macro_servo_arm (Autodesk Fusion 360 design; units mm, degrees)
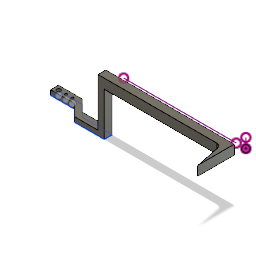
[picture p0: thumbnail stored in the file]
sketch "Sketch1" plane through (0, 0, 0) normal (0, 1, 0) x axis (1, 0, 0)
  line L1 (-10, 0) -> (-24.9061, 0)
  line L2 (-24.9061, -5) -> (-24.9061, 0)
  line L3 (-10, -5) -> (-24.9061, -5)
  line L4 (-2.9289, -7.0711) -> (-10, 0)
  line L5 (-2.9289, -12.0711) -> (-10, -5)
  line L6 (15.6446, -12.0711) -> (15.6446, -7.0711)
  line L7 (15.6446, -7.0711) -> (-2.9289, -7.0711)
  line L8 (-2.9289, -12.0711) -> (15.6446, -12.0711)
  circle C1 centre (-17.5324, -2.7002) radius 0.75
  circle C2 centre (-13.5324, -2.7002) radius 0.75
  circle C3 centre (-22.0324, -2.7002) radius 1.2
  point P6 (-17.5324, -2.7002)
  point P10 (-22.0324, -2.7002)
  dimension "d31" diameter C3 = 2.4
  dimension "d32" distance P6 P10 = 4.5
  dimension "d34" diameter C2 = 1.5
  dimension "d35" diameter C1 = 1.5
extrude "Extrude2" new body sketch "Sketch1" along normal blind 3
extrude "Extrude1" new body sketch "Sketch1" profile of L1 L2 L3 C1 C2 L4 L5 L7 L8 C3 along normal blind 3
sketch "Sketch2" plane through (0, 3, 0) normal (0, 1, 0) x axis (-1, 0, 0)
  line L1 (24.9061, 5) -> (24.9061, 0)
  line L2 (10, 5) -> (24.9061, 5)
  line L3 (2.9289, 12.0711) -> (10, 5)
  line L4 (-15.6446, 12.0711) -> (2.9289, 12.0711)
  line L5 (-15.6446, 7.0711) -> (-15.6446, 12.0711)
  line L6 (2.9289, 7.0711) -> (-15.6446, 7.0711)
  line L7 (10, 0) -> (2.9289, 7.0711)
  line L8 (24.9061, 0) -> (10, 0)
  line L9 (-11.6446, 12.0711) -> (-15.6446, 12.0711)
  line L10 (-11.6446, 7.0711) -> (-11.6446, 12.0711)
  line L11 (-15.6446, 7.0711) -> (-11.6446, 7.0711)
  line L12 (-15.6446, 12.0711) -> (-15.6446, 7.0711)
  circle C1 centre (13.5324, 2.7002) radius 0.75
  circle C2 centre (17.5324, 2.7002) radius 0.75
  circle C3 centre (22.0324, 2.7002) radius 1.2
  point P13 (-15.6446, 12.0711)
  point P14 (-11.6446, 12.0711)
  point P16 (-15.6446, 7.0711)
  dimension "d40" distance P13 P14 = 4
  dimension "d41" distance P13 P16 = 5
extrude "Extrude3" add sketch "Sketch2" profile of L4 L5 L6 L9 L10 L11 L12 along normal blind 30
sketch "Sketch3" plane through (15.6446, 0, 0) normal (1, 0, 0) x axis (0, 0, -1)
  line L1 (-7.0711, 33) -> (-7.0711, 0)
  line L2 (-12.0711, 33) -> (-7.0711, 33)
  line L3 (-12.0711, 0) -> (-12.0711, 33)
  line L4 (-7.0711, 0) -> (-12.0711, 0)
  line L5 (-7.0711, 33) -> (-12.0711, 33)
  line L6 (-7.0711, 27) -> (-7.0711, 33)
  line L7 (-12.0711, 27) -> (-7.0711, 27)
  line L8 (-12.0711, 33) -> (-12.0711, 27)
  point P6 (-12.0711, 33)
  point P7 (-7.0711, 33)
  point P9 (-12.0711, 27)
  dimension "d44" distance P6 P7 = 5
  dimension "d45" distance P6 P9 = 6
extrude "Extrude4" add sketch "Sketch3" profile of L1 L2 L3 L5 L6 L7 L8 along normal blind 76
sketch "Sketch4" plane through (0, 0, 12.0711) normal (0, 0, 1) x axis (1, 0, 0)
  line L1 (15.6446, 27) -> (15.6446, 0)
  line L2 (91.6446, 27) -> (15.6446, 27)
  line L3 (91.6446, 33) -> (91.6446, 27)
  line L4 (11.6446, 33) -> (91.6446, 33)
  line L5 (11.6446, 3) -> (11.6446, 33)
  line L6 (-2.9289, 3) -> (11.6446, 3)
  line L7 (-2.9289, 0) -> (-2.9289, 3)
  line L8 (15.6446, 0) -> (-2.9289, 0)
  line L9 (88.6446, 33) -> (91.6446, 33)
  line L10 (88.6446, 27) -> (88.6446, 33)
  line L11 (91.6446, 27) -> (88.6446, 27)
  line L12 (91.6446, 33) -> (91.6446, 27)
extrude "Extrude5" add sketch "Sketch4" profile of L2 L3 L4 L9 L10 L11 L12 distance 3
sketch "Sketch5" plane through (0, 33, 0) normal (0, 1, 0) x axis (-1, 0, 0)
  line L1 (-91.6446, 7.0711) -> (-91.6446, 15.0711)
  line L2 (-11.6446, 7.0711) -> (-91.6446, 7.0711)
  line L3 (-11.6446, 12.0711) -> (-11.6446, 7.0711)
  line L4 (-88.6446, 12.0711) -> (-11.6446, 12.0711)
  line L5 (-88.6446, 15.0711) -> (-88.6446, 12.0711)
  line L6 (-91.6446, 15.0711) -> (-88.6446, 15.0711)
  line L7 (-91.6446, 30.0711) -> (-91.6446, 15.0711)
  line L8 (-91.6446, 30.0711) -> (-88.6446, 15.0711)
  point P8 (-91.6446, 15.0711)
  point P9 (-91.6446, 30.0711)
  dimension "d50" distance P8 P9 = 15
extrude "Extrude6" add sketch "Sketch5" profile of L6 L7 L8 against normal blind 6
fillet "Fillet1" radius 3
sketch "Sketch6"
  line L1 (85.6446, 27) -> (15.6446, 27)
  line L2 (91.6446, 27) -> (91.6446, 33)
